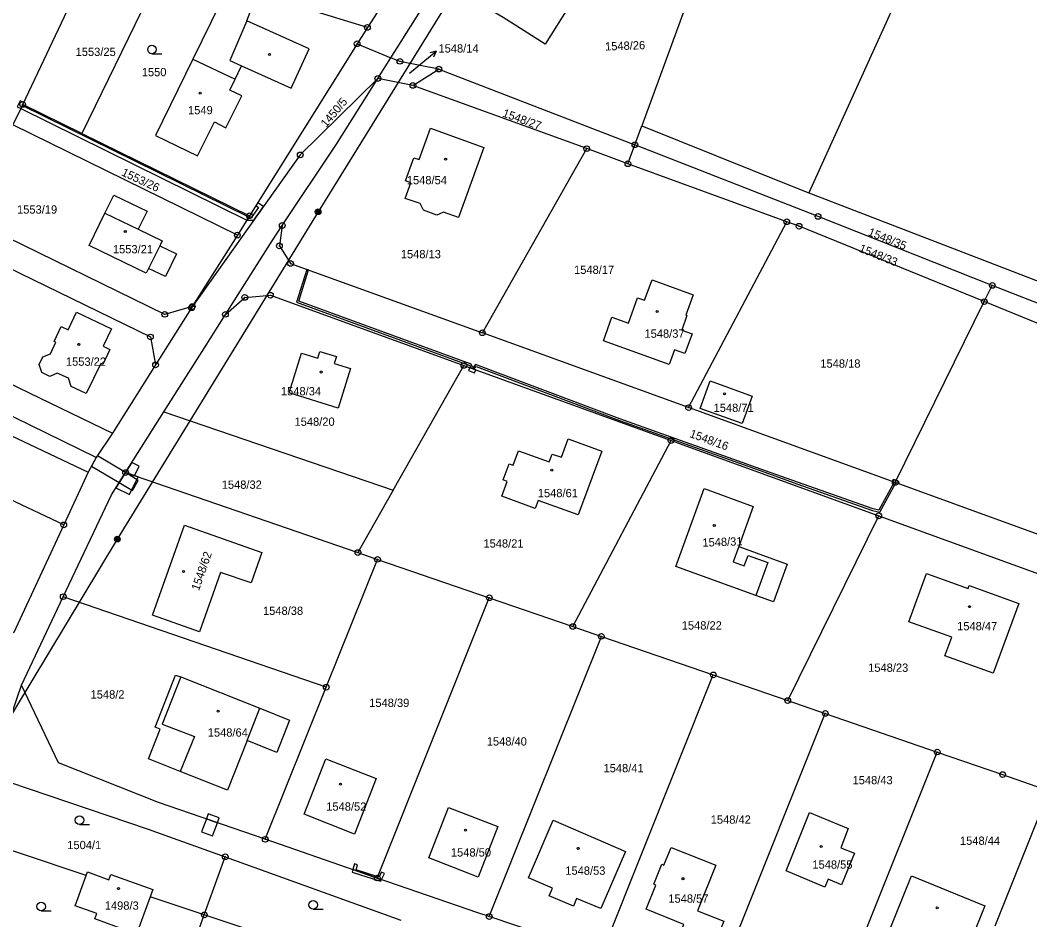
# Model space of a CAD drawing. Extents: x -587171 to -555306, y -1167727 to -1074732.
# Drawn here: x -559730.5 to -559552.9, y -1075888.7 to -1075730.3 of the extents above; entities that cross this region are included whole.
import ezdxf

# ---------------------------------------------------------------- set-up
doc = ezdxf.new("R2010")
doc.units = 0
for name, color, linetype in [('Hranice parcel', 7, 'Continuous'), ('Parcelní čísla', 7, 'Continuous'), ('Pop  PČ popisy', 7, 'Continuous'), ('Poz předměty', 7, 'Continuous'), ('Vnitřní kresba', 7, 'Continuous'), ('Věcná břemena k části', 7, 'Continuous'), ('Značky bodu BP', 7, 'Continuous'), ('Značky budov', 7, 'Continuous'), ('Značky kultur', 7, 'Continuous')]:
    doc.layers.add(name, color=color, linetype=linetype)

msp = doc.modelspace()

# ---------------------------------------------------------------- linework, layer by layer
at = {"layer": 'Hranice parcel'}
for p, q in [((-559567.31, -1075706.86), (-559591.71, -1075760.7)), ((-559658.49, -1075714.7), (-559669.42, -1075731.6)), ((-559730.08, -1075745.15), (-559717.64, -1075718.96)), ((-559706.21, -1075722.62), (-559719.69, -1075750.25)), ((-559612.08, -1075724.14), (-559621.14, -1075748.94)), ((-559669.42, -1075731.6), (-559688.83, -1075725.64)), ((-559669.42, -1075731.6), (-559671.22, -1075734.47)), ((-559671.22, -1075734.47), (-559690.16, -1075764.76)), ((-559671.22, -1075734.47), (-559665.28, -1075736.92)), ((-559667.58, -1075740.58), (-559665.28, -1075736.92)), ((-559661.42, -1075741.8), (-559656.84, -1075738.94)), ((-559656.84, -1075738.94), (-559622.35, -1075752.26)), ((-559661.42, -1075741.8), (-559667.58, -1075740.58)), ((-559630.83, -1075752.94), (-559661.42, -1075741.8)), ((-559730.08, -1075745.15), (-559731.8, -1075748.76)), ((-559719.69, -1075750.25), (-559730.08, -1075745.15)), ((-559692.3, -1075768.16), (-559731.8, -1075748.76)), ((-559622.35, -1075752.26), (-559621.14, -1075748.94)), ((-559621.14, -1075748.94), (-559595.12, -1075759.39)), ((-559719.69, -1075750.25), (-559690.16, -1075764.76)), ((-559649.19, -1075785.36), (-559630.83, -1075752.94)), ((-559623.57, -1075755.59), (-559630.83, -1075752.94)), ((-559623.57, -1075755.59), (-559622.35, -1075752.26)), ((-559595.61, -1075765.81), (-559623.57, -1075755.59)), ((-559595.12, -1075759.39), (-559591.71, -1075760.7)), ((-559591.71, -1075760.7), (-559523.02, -1075787.2)), ((-559612.9, -1075798.53), (-559595.61, -1075765.81)), ((-559692.3, -1075768.16), (-559700.23, -1075780.74)), ((-559560.86, -1075779.87), (-559559.45, -1075777.02)), ((-559524.66, -1075790.79), (-559559.45, -1075777.02)), ((-559576.54, -1075811.71), (-559560.86, -1075779.87)), ((-559700.36, -1075780.95), (-559706.7, -1075791.01)), ((-559700.23, -1075780.74), (-559700.36, -1075780.95)), ((-559612.9, -1075798.53), (-559649.19, -1075785.36)), ((-559749.98, -1075785.74), (-559714.26, -1075803.02)), ((-559717.12, -1075807.32), (-559752.15, -1075790.16)), ((-559706.7, -1075791.01), (-559714.26, -1075803.02)), ((-559664.87, -1075813.06), (-559652.44, -1075791.1)), ((-559652.44, -1075791.1), (-559615.97, -1075804.33)), ((-559753.71, -1075793.22), (-559718.54, -1075809.9)), ((-559711.98, -1075809.97), (-559705.24, -1075799.29)), ((-559705.24, -1075799.29), (-559664.87, -1075813.06)), ((-559576.54, -1075811.71), (-559612.9, -1075798.53)), ((-559722.85, -1075819.18), (-559758.36, -1075802.33)), ((-559714.26, -1075803.02), (-559717.12, -1075807.32)), ((-559633.27, -1075837.07), (-559615.97, -1075804.33)), ((-559615.97, -1075804.33), (-559579.43, -1075817.58)), ((-559717.12, -1075807.32), (-559718.54, -1075809.9)), ((-559718.54, -1075809.9), (-559722.85, -1075819.18)), ((-559711.98, -1075809.97), (-559671.09, -1075824.05)), ((-559664.87, -1075813.06), (-559671.09, -1075824.05)), ((-559595.45, -1075850.1), (-559579.43, -1075817.58)), ((-559722.85, -1075819.18), (-559731.69, -1075838.23)), ((-559671.09, -1075824.05), (-559667.64, -1075825.24)), ((-559676.66, -1075847.75), (-559667.64, -1075825.24)), ((-559667.64, -1075825.24), (-559647.96, -1075832.01)), ((-559730.31, -1075847.37), (-559722.94, -1075831.81)), ((-559676.66, -1075847.75), (-559722.94, -1075831.81)), ((-559667.68, -1075881.34), (-559647.96, -1075832.01)), ((-559647.96, -1075832.01), (-559633.27, -1075837.07)), ((-559633.27, -1075837.07), (-559628.25, -1075838.8)), ((-559647.97, -1075888.13), (-559628.25, -1075838.8)), ((-559628.25, -1075838.8), (-559608.55, -1075845.59)), ((-559628.22, -1075894.76), (-559608.55, -1075845.59)), ((-559608.55, -1075845.59), (-559595.45, -1075850.1)), ((-559735.95, -1075863.92), (-559730.31, -1075847.37)), ((-559687.39, -1075874.53), (-559676.66, -1075847.75)), ((-559595.45, -1075850.1), (-559588.84, -1075852.37)), ((-559608.45, -1075901.38), (-559588.84, -1075852.37)), ((-559588.84, -1075852.37), (-559569.13, -1075859.16)), ((-559588.69, -1075908), (-559569.13, -1075859.16)), ((-559558.96, -1075889.73), (-559549.44, -1075865.97)), ((-559667.68, -1075881.34), (-559687.39, -1075874.53)), ((-559698.12, -1075887.83), (-559694.43, -1075877.61)), ((-559694.43, -1075877.61), (-559663.54, -1075888.77)), ((-559698.12, -1075887.83), (-559707.66, -1075884.64)), ((-559705.7, -1075908.82), (-559698.12, -1075887.83)), ((-559672.82, -1075896.26), (-559698.12, -1075887.83)), ((-559628.22, -1075894.76), (-559647.97, -1075888.13))]:
    msp.add_line(p, q, dxfattribs=at)
for points in [[(-559665.28, -1075736.92), (-559663.49, -1075734.09), (-559648, -1075709.41)], [(-559644.07, -1075724.48), (-559638.67, -1075715.86), (-559629.89, -1075721.34), (-559638.12, -1075734.52), (-559645.53, -1075729.87), (-559646.91, -1075729.02), (-559644.07, -1075724.48)], [(-559693.75, -1075724.12), (-559700.15, -1075737.2), (-559706.68, -1075750.61), (-559699.32, -1075754.18), (-559696.3, -1075748.24), (-559694.33, -1075749.28), (-559691.54, -1075743.65), (-559693.63, -1075742.63), (-559692.68, -1075740.72), (-559691.59, -1075738.35), (-559682.86, -1075742.27), (-559679.68, -1075735.38), (-559690.61, -1075730.46), (-559688.83, -1075725.64)], [(-559656.84, -1075738.94), (-559663.7, -1075737.57), (-559665.28, -1075736.92)], [(-559667.58, -1075740.58), (-559681.23, -1075754.03), (-559700.36, -1075780.95)], [(-559684.4, -1075766.45), (-559674.88, -1075752.15), (-559667.58, -1075740.58)], [(-559662.73, -1075758.61), (-559661.24, -1075754.53), (-559660.32, -1075754.87), (-559658.3, -1075749.32), (-559648.9, -1075752.74), (-559653.39, -1075765.08), (-559656.01, -1075764.13), (-559657.22, -1075764.62), (-559659.57, -1075763.78), (-559660.16, -1075762.62), (-559662.79, -1075761.69), (-559661.79, -1075758.95), (-559662.73, -1075758.61)], [(-559559.45, -1075777.02), (-559590.11, -1075764.88), (-559622.35, -1075752.26)], [(-559700.23, -1075780.74), (-559705.08, -1075782.11), (-559735.58, -1075767.22), (-559737.76, -1075760.91)], [(-559709.73, -1075767.14), (-559705.55, -1075769.17), (-559705.97, -1075770.03), (-559703.02, -1075771.47), (-559704.96, -1075775.46), (-559707.91, -1075774.03), (-559708.32, -1075774.87), (-559718.38, -1075769.97), (-559715.61, -1075764.27), (-559714.03, -1075761.11), (-559708.2, -1075763.95), (-559709.73, -1075767.14)], [(-559690.16, -1075764.76), (-559691.23, -1075766.46), (-559692.3, -1075768.16)], [(-559560.86, -1075779.87), (-559593.45, -1075766.6), (-559595.61, -1075765.81)], [(-559694.39, -1075782.11), (-559686.19, -1075769.14), (-559684.4, -1075766.45)], [(-559684.4, -1075766.45), (-559684.9, -1075770.06), (-559682.95, -1075773.15), (-559649.19, -1075785.36)], [(-559743.97, -1075773.56), (-559737.63, -1075771.45), (-559707.59, -1075786.09), (-559706.7, -1075791.01)], [(-559627.89, -1075786.75), (-559626.4, -1075782.6), (-559623.46, -1075783.66), (-559621.86, -1075779.19), (-559620.64, -1075779.63), (-559619.33, -1075776.05), (-559612.08, -1075778.66), (-559613.37, -1075782.25), (-559613.21, -1075782.33), (-559614.11, -1075784.89), (-559612.28, -1075785.56), (-559613.53, -1075789.03), (-559615.36, -1075788.37), (-559616.3, -1075790.94), (-559627.89, -1075786.75)], [(-559694.39, -1075782.11), (-559691, -1075779.13), (-559686.48, -1075778.75), (-559652.44, -1075791.1)], [(-559524.66, -1075790.79), (-559526.13, -1075794.02), (-559560.86, -1075779.87)], [(-559721.56, -1075794.79), (-559722.04, -1075793.37), (-559724.03, -1075792.46), (-559725.32, -1075793.03), (-559726.73, -1075792.33), (-559727.2, -1075790.94), (-559726.53, -1075789.56), (-559725.17, -1075789.04), (-559724.22, -1075787.02), (-559724.55, -1075786.87), (-559723.29, -1075784.24), (-559722.08, -1075784.82), (-559720.59, -1075781.72), (-559714.46, -1075784.63), (-559715.94, -1075787.73), (-559714.73, -1075788.32), (-559715.99, -1075790.91), (-559716.31, -1075790.76), (-559718.88, -1075796.03), (-559721.56, -1075794.79)], [(-559705.24, -1075799.29), (-559698.1, -1075787.99), (-559694.39, -1075782.11)], [(-559675.24, -1075790.76), (-559672.37, -1075791.67), (-559674.57, -1075798.64), (-559683.2, -1075795.91), (-559681, -1075788.94), (-559678.14, -1075789.85), (-559677.76, -1075788.63), (-559674.86, -1075789.55), (-559675.24, -1075790.76)], [(-559609.12, -1075793.81), (-559601.69, -1075796.5), (-559603.47, -1075801.33), (-559610.88, -1075798.66), (-559609.12, -1075793.81)], [(-559645.5, -1075811.25), (-559644.47, -1075808.44), (-559643.77, -1075808.68), (-559642.82, -1075806.12), (-559637.44, -1075808.1), (-559636.91, -1075806.7), (-559635.28, -1075807.28), (-559634.07, -1075804), (-559628.19, -1075806.17), (-559632.33, -1075817.41), (-559639.38, -1075814.88), (-559639.89, -1075816.26), (-559645.75, -1075814.1), (-559644.8, -1075811.52), (-559645.5, -1075811.25)], [(-559722.94, -1075831.81), (-559714.46, -1075813.89), (-559711.98, -1075809.97)], [(-559528.88, -1075822.62), (-559534.52, -1075820.57), (-559535.7, -1075822.54), (-559537.52, -1075823.92), (-559539.74, -1075824.51), (-559542.01, -1075824.24), (-559576.54, -1075811.71)], [(-559604.08, -1075823), (-559595.54, -1075826.07), (-559597.96, -1075832.72), (-559601.06, -1075831.59), (-559615.13, -1075826.48), (-559610.15, -1075812.76), (-559601.51, -1075815.93), (-559604.08, -1075823)], [(-559579.43, -1075817.58), (-559544.03, -1075830.42), (-559541.96, -1075831.6), (-559540.5, -1075833.5), (-559539.9, -1075835.81), (-559540.25, -1075838.17), (-559534.61, -1075840.22)], [(-559698.96, -1075837.98), (-559707.21, -1075835.07), (-559701.61, -1075819.25), (-559688.02, -1075824.03), (-559689.86, -1075829.39), (-559695.26, -1075827.53), (-559698.96, -1075837.98)], [(-559559.27, -1075845.29), (-559567.78, -1075842.2), (-559566.59, -1075838.95), (-559574.11, -1075836.24), (-559571.03, -1075827.72), (-559563.71, -1075830.35), (-559563.54, -1075829.86), (-559554.79, -1075833), (-559559.27, -1075845.29)], [(-559703.18, -1075845.61), (-559702.24, -1075845.91), (-559688.33, -1075851.43), (-559683.1, -1075853.55), (-559685.36, -1075859.25), (-559690.58, -1075857.16), (-559694.06, -1075865.9), (-559702.34, -1075862.61), (-559707.95, -1075860.38), (-559705.86, -1075855.12), (-559706.79, -1075854.76), (-559703.18, -1075845.61)], [(-559687.39, -1075874.53), (-559706.2, -1075868.03), (-559723.8, -1075861.04), (-559730.31, -1075847.37)], [(-559569.13, -1075859.16), (-559557.63, -1075863.12), (-559549.44, -1075865.97)], [(-559680.56, -1075870.09), (-559676.72, -1075860.33), (-559667.9, -1075863.81), (-559671.71, -1075873.61), (-559680.56, -1075870.09)], [(-559735.95, -1075863.92), (-559732.58, -1075864.43), (-559707.97, -1075872.72), (-559694.43, -1075877.61)], [(-559646.47, -1075872.28), (-559649.9, -1075881.17), (-559658.58, -1075877.79), (-559655.15, -1075868.94), (-559646.47, -1075872.28)], [(-559595.71, -1075880.07), (-559591.62, -1075869.82), (-559584.82, -1075872.65), (-559586.12, -1075876), (-559583.7, -1075876.96), (-559585.96, -1075882.56), (-559588.36, -1075881.57), (-559588.94, -1075882.94), (-559595.71, -1075880.07)], [(-559718.92, -1075880.89), (-559742.59, -1075873), (-559743.87, -1075872.57)], [(-559636.74, -1075871.16), (-559624, -1075876.65), (-559628.33, -1075886.73), (-559632.6, -1075884.95), (-559633.17, -1075886.31), (-559637.41, -1075884.5), (-559636.85, -1075883.12), (-559641.07, -1075881.31), (-559636.74, -1075871.16)], [(-559620.34, -1075886.84), (-559618.64, -1075882.6), (-559619.02, -1075882.45), (-559617.61, -1075878.92), (-559617.24, -1075879.07), (-559615.99, -1075875.94), (-559608.11, -1075879.08), (-559611.3, -1075887.1), (-559606.72, -1075888.93), (-559608.99, -1075894.68), (-559614.83, -1075892.34), (-559613.71, -1075889.55), (-559620.34, -1075886.84)], [(-559707.66, -1075884.64), (-559710.03, -1075891.2), (-559717.41, -1075888.55), (-559717.05, -1075887.58), (-559720.84, -1075886.26), (-559718.92, -1075880.89)], [(-559718.92, -1075880.89), (-559718.7, -1075880.28), (-559714.91, -1075881.68), (-559714.57, -1075880.7), (-559707.2, -1075883.37), (-559707.66, -1075884.64)], [(-559647.97, -1075888.13), (-559649.99, -1075887.45), (-559667.68, -1075881.34)], [(-559577.95, -1075891.58), (-559573.65, -1075880.98), (-559560.77, -1075886.21), (-559565, -1075896.76), (-559577.95, -1075891.58)]]:
    msp.add_lwpolyline(points, dxfattribs=at)
at = {"layer": 'Pop  PČ popisy'}
for p, q in [((-559659.64, -1075737.71), (-559657.34, -1075735.78)), ((-559657.34, -1075735.78), (-559658.43, -1075736.04)), ((-559657.34, -1075735.78), (-559657.79, -1075736.81)), ((-559662, -1075739.67), (-559659.64, -1075737.71))]:
    msp.add_line(p, q, dxfattribs=at)
at = {"layer": 'Poz předměty'}
for p, q in [((-559625.05, -1075678.03), (-559678.09, -1075764.05)), ((-559678.09, -1075764.05), (-559713.43, -1075821.67)), ((-559713.43, -1075821.67), (-559734.8, -1075857.12))]:
    msp.add_line(p, q, dxfattribs=at)
for centre, radius in [((-559678.09, -1075764.05), 0.5), ((-559678.09, -1075764.05), 0.4), ((-559678.09, -1075764.05), 0.3), ((-559678.09, -1075764.05), 0.2), ((-559678.09, -1075764.05), 0.1), ((-559713.43, -1075821.67), 0.5), ((-559713.43, -1075821.67), 0.4), ((-559713.43, -1075821.67), 0.3), ((-559713.43, -1075821.67), 0.2), ((-559713.43, -1075821.67), 0.1)]:
    msp.add_circle(centre, radius, dxfattribs=at)
at = {"layer": 'Vnitřní kresba'}
for p, q in [((-559690.61, -1075730.46), (-559693.62, -1075737.43)), ((-559700.15, -1075737.2), (-559692.68, -1075740.72)), ((-559693.62, -1075737.43), (-559691.59, -1075738.35)), ((-559715.61, -1075764.27), (-559709.73, -1075767.14)), ((-559705.97, -1075770.03), (-559707.91, -1075774.03)), ((-559702.24, -1075845.91), (-559705.52, -1075854.26)), ((-559690.58, -1075857.16), (-559688.33, -1075851.43)), ((-559705.52, -1075854.26), (-559699.87, -1075856.43)), ((-559699.87, -1075856.43), (-559702.34, -1075862.61))]:
    msp.add_line(p, q, dxfattribs=at)
msp.add_lwpolyline([(-559604.08, -1075823), (-559605.05, -1075825.67), (-559603.09, -1075826.4), (-559602.41, -1075824.54), (-559598.95, -1075825.8), (-559601.06, -1075831.59)], dxfattribs=at)
at = {"layer": 'Věcná břemena k části'}
for points in [[(-559730.43, -1075745.88), (-559690.65, -1075765.53), (-559690.3, -1075764.99), (-559730.17, -1075745.34), (-559730.08, -1075745.15), (-559729.93, -1075744.83), (-559730.53, -1075744.53), (-559731.05, -1075745.57)], [(-559690.3, -1075764.99), (-559690.65, -1075765.53), (-559689.41, -1075765.54), (-559687.71, -1075763.15), (-559688.72, -1075762.46), (-559689.04, -1075762.97), (-559688.56, -1075763.3), (-559689.74, -1075764.94)], [(-559576.54, -1075811.71), (-559576.74, -1075811.64), (-559579.41, -1075816.57), (-559580.44, -1075816.35), (-559593.72, -1075811.64), (-559599.39, -1075809.64), (-559624.97, -1075800.5), (-559650.4, -1075790.91), (-559650.89, -1075791.54), (-559651.18, -1075790.85), (-559681.5, -1075779.77), (-559679.79, -1075774.29), (-559680.07, -1075774.19), (-559681.87, -1075779.95), (-559651.41, -1075791.09), (-559651.22, -1075791.54), (-559650.67, -1075791.74), (-559650.3, -1075791.27), (-559625.08, -1075800.78), (-559599.49, -1075809.92), (-559593.82, -1075811.93), (-559580.52, -1075816.64), (-559579.25, -1075816.91), (-559576.44, -1075811.75)], [(-559651.6, -1075791.98), (-559650.56, -1075792.39), (-559650.35, -1075791.86), (-559650.67, -1075791.74), (-559651.22, -1075791.54), (-559651.4, -1075791.48)], [(-559713.09, -1075811.72), (-559711.98, -1075809.97), (-559716.94, -1075807.04), (-559717.12, -1075807.32), (-559717.95, -1075808.82)], [(-559710.86, -1075808.2), (-559711.98, -1075809.97), (-559710.4, -1075810.51), (-559709.57, -1075808.85)], [(-559711.29, -1075813.84), (-559709.74, -1075810.74), (-559711.98, -1075809.97), (-559713.68, -1075812.66)], [(-559709.73, -1075811.35), (-559711.98, -1075809.97), (-559713.09, -1075811.72), (-559710.77, -1075813.11)], [(-559576.89, -1075811.16), (-559577.03, -1075811.53), (-559576.74, -1075811.64), (-559576.54, -1075811.71), (-559576.37, -1075811.37)], [(-559575.85, -1075811.57), (-559576.37, -1075811.37), (-559576.54, -1075811.71), (-559576.44, -1075811.75), (-559575.98, -1075811.91)], [(-559696.68, -1075873.94), (-559695.82, -1075871.62), (-559697.74, -1075870.95), (-559698.59, -1075873.23)], [(-559697.41, -1075870.07), (-559697.74, -1075870.95), (-559695.82, -1075871.62), (-559695.51, -1075870.77)], [(-559671.99, -1075879.85), (-559667.68, -1075881.34), (-559667.59, -1075881.12), (-559671.38, -1075879.9), (-559671.13, -1075879), (-559671.71, -1075878.84)], [(-559671.99, -1075879.85), (-559672.12, -1075880.3), (-559667.1, -1075881.9), (-559666.94, -1075881.6), (-559667.68, -1075881.34)], [(-559667.59, -1075881.12), (-559667.68, -1075881.34), (-559666.94, -1075881.6), (-559666.41, -1075880.55), (-559666.96, -1075880.32), (-559667.4, -1075881.18)]]:
    msp.add_lwpolyline(points, close=True, dxfattribs=at)
at = {"layer": 'Značky bodu BP'}
for centre, radius in [((-559669.42, -1075731.6), 0.5), ((-559669.42, -1075731.6), 0.0303), ((-559671.22, -1075734.47), 0.5), ((-559671.22, -1075734.47), 0.0303), ((-559663.7, -1075737.57), 0.5), ((-559663.7, -1075737.57), 0.0303), ((-559656.84, -1075738.94), 0.5), ((-559656.84, -1075738.94), 0.0303), ((-559667.58, -1075740.58), 0.5), ((-559667.58, -1075740.58), 0.0303), ((-559661.42, -1075741.8), 0.5), ((-559661.42, -1075741.8), 0.0303), ((-559730.08, -1075745.15), 0.5), ((-559730.08, -1075745.15), 0.0303), ((-559622.35, -1075752.26), 0.5), ((-559681.23, -1075754.03), 0.5), ((-559630.83, -1075752.94), 0.5), ((-559630.83, -1075752.94), 0.0303), ((-559622.35, -1075752.26), 0.0303), ((-559681.23, -1075754.03), 0.0303), ((-559623.57, -1075755.59), 0.5), ((-559623.57, -1075755.59), 0.0303), ((-559690.16, -1075764.76), 0.5), ((-559690.16, -1075764.76), 0.0303), ((-559684.4, -1075766.45), 0.5), ((-559595.61, -1075765.81), 0.5), ((-559595.61, -1075765.81), 0.0303), ((-559593.45, -1075766.6), 0.5), ((-559590.11, -1075764.88), 0.5), ((-559590.11, -1075764.88), 0.0303), ((-559692.3, -1075768.16), 0.5), ((-559684.4, -1075766.45), 0.0303), ((-559593.45, -1075766.6), 0.0303), ((-559692.3, -1075768.16), 0.0303), ((-559684.9, -1075770.06), 0.5), ((-559684.9, -1075770.06), 0.0303), ((-559682.95, -1075773.15), 0.5), ((-559682.95, -1075773.15), 0.0303), ((-559559.45, -1075777.02), 0.5), ((-559686.48, -1075778.75), 0.5), ((-559559.45, -1075777.02), 0.0303), ((-559700.23, -1075780.74), 0.5), ((-559691, -1075779.13), 0.5), ((-559691, -1075779.13), 0.0303), ((-559686.48, -1075778.75), 0.0303), ((-559560.86, -1075779.87), 0.5), ((-559560.86, -1075779.87), 0.0303), ((-559705.08, -1075782.11), 0.5), ((-559705.08, -1075782.11), 0.0303), ((-559700.36, -1075780.95), 0.5), ((-559700.36, -1075780.95), 0.0303), ((-559700.23, -1075780.74), 0.0303), ((-559694.39, -1075782.11), 0.5), ((-559694.39, -1075782.11), 0.0303), ((-559707.59, -1075786.09), 0.5), ((-559649.19, -1075785.36), 0.5), ((-559649.19, -1075785.36), 0.0303), ((-559707.59, -1075786.09), 0.0303), ((-559706.7, -1075791.01), 0.5), ((-559706.7, -1075791.01), 0.0303), ((-559652.44, -1075791.1), 0.5), ((-559652.44, -1075791.1), 0.0303), ((-559612.9, -1075798.53), 0.5), ((-559612.9, -1075798.53), 0.0303), ((-559615.97, -1075804.33), 0.5), ((-559615.97, -1075804.33), 0.0303), ((-559711.98, -1075809.97), 0.5), ((-559711.98, -1075809.97), 0.0303), ((-559576.54, -1075811.71), 0.5), ((-559576.54, -1075811.71), 0.0303), ((-559579.43, -1075817.58), 0.5), ((-559579.43, -1075817.58), 0.0303), ((-559722.85, -1075819.18), 0.5), ((-559722.85, -1075819.18), 0.0303), ((-559671.09, -1075824.05), 0.5), ((-559671.09, -1075824.05), 0.0303), ((-559667.64, -1075825.24), 0.5), ((-559667.64, -1075825.24), 0.0303), ((-559722.94, -1075831.81), 0.5), ((-559722.94, -1075831.81), 0.0303), ((-559647.96, -1075832.01), 0.5), ((-559647.96, -1075832.01), 0.0303), ((-559633.27, -1075837.07), 0.5), ((-559633.27, -1075837.07), 0.0303), ((-559628.25, -1075838.8), 0.5), ((-559628.25, -1075838.8), 0.0303), ((-559608.55, -1075845.59), 0.5), ((-559608.55, -1075845.59), 0.0303), ((-559676.66, -1075847.75), 0.5), ((-559676.66, -1075847.75), 0.0303), ((-559595.45, -1075850.1), 0.5), ((-559595.45, -1075850.1), 0.0303), ((-559588.84, -1075852.37), 0.5), ((-559588.84, -1075852.37), 0.0303), ((-559569.13, -1075859.16), 0.5), ((-559569.13, -1075859.16), 0.0303), ((-559557.63, -1075863.12), 0.5), ((-559557.63, -1075863.12), 0.0303), ((-559687.39, -1075874.53), 0.5), ((-559687.39, -1075874.53), 0.0303), ((-559694.43, -1075877.61), 0.5), ((-559694.43, -1075877.61), 0.0303), ((-559667.68, -1075881.34), 0.5), ((-559667.68, -1075881.34), 0.0303), ((-559698.12, -1075887.83), 0.5), ((-559698.12, -1075887.83), 0.0303), ((-559647.97, -1075888.13), 0.5), ((-559647.97, -1075888.13), 0.0303)]:
    msp.add_circle(centre, radius, dxfattribs=at)
at = {"layer": 'Značky budov'}
for centre in [(-559686.64, -1075736.36), (-559698.83, -1075743.15), (-559655.65, -1075754.8), (-559712.02, -1075767.5), (-559618.44, -1075781.59), (-559720.18, -1075787.39), (-559677.56, -1075792.26), (-559606.59, -1075796.09), (-559636.95, -1075809.56), (-559608.37, -1075819.29), (-559701.79, -1075827.4), (-559563.45, -1075833.57), (-559695.68, -1075851.99), (-559674.14, -1075864.84), (-559652.16, -1075872.93), (-559632.31, -1075876.12), (-559589.57, -1075875.8), (-559613.88, -1075881.46), (-559713.21, -1075883.21), (-559569.17, -1075886.57)]:
    msp.add_circle(centre, 0.175, dxfattribs=at)
at = {"layer": 'Značky kultur'}
for p, q in [((-559707.33, -1075736.24), (-559705.58, -1075736.24)), ((-559720.07, -1075871.9), (-559718.32, -1075871.9)), ((-559678.95, -1075886.8), (-559677.2, -1075886.8)), ((-559726.81, -1075887.1), (-559725.06, -1075887.1))]:
    msp.add_line(p, q, dxfattribs=at)
for centre in [(-559707.33, -1075735.49), (-559720.07, -1075871.15), (-559726.81, -1075886.35), (-559678.95, -1075886.05)]:
    msp.add_circle(centre, 0.75, dxfattribs=at)

# ---------------------------------------------------------------- texts
at = {"layer": 'Parcelní čísla'}
for s, rotation, p in [('1548/26', 2, (-559627.57, -1075735.67)), ('1450/5', 50, (-559676.66, -1075749.31)), ('1548/27', 340, (-559645.76, -1075747.25)), ('1553/26', 335, (-559712.82, -1075757.6)), ('1548/35', 338, (-559581.44, -1075768.16)), ('1548/33', 338, (-559583.03, -1075771.03)), ('1548/16', 340, (-559612.83, -1075803.68)), ('1548/31', 2, (-559610.44, -1075823.02)), ('1548/62', 71, (-559699.06, -1075830.85))]:
    msp.add_text(s, height=1.46, rotation=rotation, dxfattribs=at).set_placement(p)
for s, p in [('1553/25', (-559720.76, -1075736.62)), ('1548/14', (-559656.91, -1075736.02)), ('1550', (-559709.12, -1075740.19)), ('1549', (-559700.98, -1075746.89)), ('1548/54', (-559662.48, -1075759.21)), ('1553/19', (-559731.07, -1075764.38)), ('1553/21', (-559714.2, -1075771.37)), ('1548/13', (-559663.54, -1075772.23)), ('1548/17', (-559633.05, -1075774.99)), ('1548/37', (-559620.66, -1075786.23)), ('1553/22', (-559722.47, -1075791.16)), ('1548/18', (-559589.71, -1075791.5)), ('1548/34', (-559684.63, -1075796.37)), ('1548/71', (-559608.49, -1075799.29)), ('1548/20', (-559682.24, -1075801.73)), ('1548/32', (-559695.05, -1075812.82)), ('1548/61', (-559639.43, -1075814.3)), ('1548/21', (-559649, -1075823.17)), ('1548/38', (-559687.79, -1075835.02)), ('1548/22', (-559614.1, -1075837.6)), ('1548/47', (-559565.64, -1075837.73)), ('1548/23', (-559581.3, -1075845.04)), ('1548/2', (-559718.13, -1075849.75)), ('1548/39', (-559669.1, -1075851.23)), ('1548/64', (-559697.51, -1075856.45)), ('1548/40', (-559648.41, -1075858.02)), ('1548/41', (-559627.86, -1075862.72)), ('1548/43', (-559584.04, -1075864.84)), ('1548/52', (-559676.66, -1075869.49)), ('1548/42', (-559609, -1075871.78)), ('1548/44', (-559565.14, -1075875.5)), ('1504/1', (-559722.23, -1075876.26)), ('1548/50', (-559654.72, -1075877.56)), ('1548/53', (-559634.59, -1075880.77)), ('1548/55', (-559591.11, -1075879.7)), ('1548/57', (-559616.46, -1075885.69)), ('1498/3', (-559715.63, -1075886.92))]:
    msp.add_text(s, height=1.46, dxfattribs=at).set_placement(p)

doc.saveas('drawing.dxf')
